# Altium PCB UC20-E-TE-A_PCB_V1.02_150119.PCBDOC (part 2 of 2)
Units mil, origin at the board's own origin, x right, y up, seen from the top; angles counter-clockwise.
Board outline 1460.63 x 2271.65 mil, 4 copper layers (Top, Inner Layer 2, Inner Layer 3, Bottom), stack 35.4 mil thick; 44 components, 79 nets, 323 pads, 599 vias.
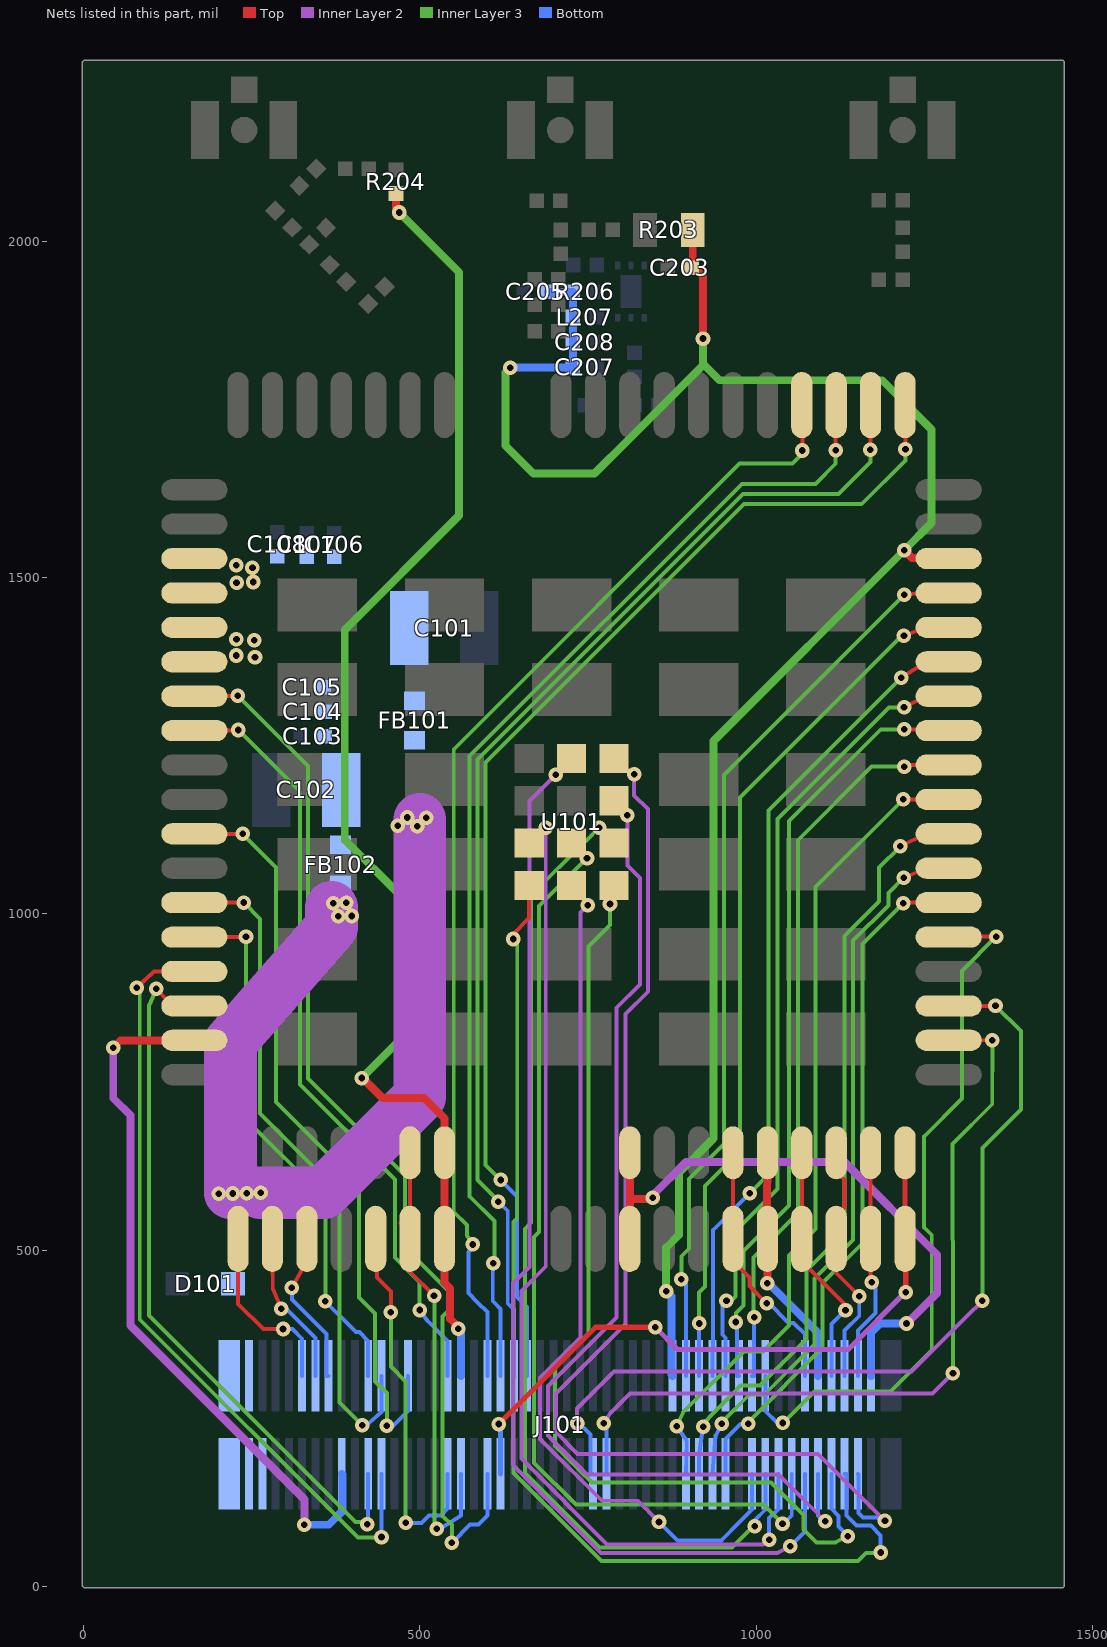
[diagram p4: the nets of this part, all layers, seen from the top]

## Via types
v1: diameter 21.65, hole 9.84, Top to Bottom, 599 vias

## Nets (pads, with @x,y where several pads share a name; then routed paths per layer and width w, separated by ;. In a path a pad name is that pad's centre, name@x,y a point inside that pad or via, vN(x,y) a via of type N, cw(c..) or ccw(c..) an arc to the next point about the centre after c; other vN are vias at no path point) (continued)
JTAG_RESOUT_N: J101.9 U101.100 | length 1483.6
  Top w5.91: v1(782.85,1014.91) 782.85,1038.69 786.63,1042.47 U101.100@788.64,1042.47
  Inner Layer 3 w5.91: v1(782.85,1014.91) 782.85,983.52 750.83,951.5 750.83,376.92 701.05,327.15 701.05,209.44 755.77,154.71 1022.55,154.71 1070.94,106.32 1070.94,84.29 1089.99,65.25 1118,65.25 ; 1118.01,65.26 v1(1136.59,74.65)
  Bottom w5.91: J101.9@1112.2,167.32 1112.2,115.42 1122.71,104.91 1122.71,88.74 v1(1136.59,74.65)
JTAG_RTCK: J101.13 U101.90 | length 1672.4
  Top w5.91: v1(702.23,1207.32) U101.90@725.64,1231.44
  Inner Layer 2 w5.91: v1(702.23,1207.32) 663.08,1168.18 663.08,474.67 638.62,450.21 638.62,180.75 769.65,49.72 1032.32,49.72 v1(1050.69,59.33)
  Bottom w5.91: v1(1050.69,59.33) 1072.83,81.47 J101.13@1072.83,167.32
JTAG_TCK: J101.15 U101.96 | length 1485.7
  Top w3.94: U101.96@725.64,1105.46 726.01,1105.09 738.08,1093.02 v1(748.61,1083.02)
  Top w5.91: U101.96@725.64,1105.46 726.01,1105.46 726.01,1105.09 726.01,1101.59 727.74,1101.59 v1(748.61,1083.02)
  Inner Layer 3 w5.91: v1(748.61,1083.02) 677.43,1011.84 677.43,527.3 670.01,519.88 670.01,183.32 731.93,121.4 1011.31,121.4 v1(1039.41,93.31)
  Bottom w5.91: v1(1039.41,93.31) 1041.24,93.31 1053.15,105.22 J101.15@1053.15,167.32
JTAG_TDI: J101.19 U101.97 | length 1522.4
  Top w5.91: v1(766.75,1128.28) U101.97@788.64,1105.46
  Inner Layer 3 w5.91: v1(766.75,1128.28) 746.96,1108.5 746.25,1108.5 665.62,1027.87 665.62,540.87 656.55,531.8 656.55,168.7 767.49,57.76 964.27,57.76 995.59,89.08 v1(997.94,89.08)
  Bottom w5.91: v1(997.94,89.08) 997.94,98.04 1013.78,113.88 J101.19@1013.78,167.32
JTAG_TDO: J101.11 U101.94 | length 1557.8
  Top w5.91: U101.94@788.64,1168.45 v1(808.74,1146.88)
  Inner Layer 2 w5.91: v1(808.74,1146.88) 808.74,1072.38 827.32,1053.8 827.32,895.41 792.47,860.55 792.47,399.62 690.58,297.73 690.58,224.32 748.9,166 1033.78,166 v1(1103.02,96.76)
  Bottom w5.91: J101.11@1092.52,167.32 1092.52,105.22 1100.98,96.76 v1(1103.02,96.76)
JTAG_TMS: J101.17 U101.95 | length 1515.7
  Top w5.91: U101.95@662.65,1105.46 668.75,1111.56 670.54,1111.56 v1(687.28,1128.31)
  Inner Layer 2 w5.91: v1(687.28,1128.31) 687.28,475.48 650.96,439.16 650.96,189.82 778.57,62.2 1010.12,62.2 1017.3,69.38 v1(1019.45,69.41)
  Bottom w5.91: v1(1019.45,69.41) 1019.45,101.3 1033.46,115.31 J101.17@1033.46,167.32
JTAG_TRST: J101.21 U101.99 | length 1310.8
  Top w5.91: U101.99@725.64,1042.47 v1(749.58,1012.85)
  Inner Layer 2 w5.91: v1(749.58,1012.85) 739.09,1002.36 739.09,369.97 678.77,309.64 678.77,219.42 770.92,127.27 824.19,127.27 v1(855.71,95.75)
  Bottom w5.91: v1(855.71,95.75) 883.01,68.45 948.33,68.45 976.46,96.57 994.09,114.24 J101.21@994.09,167.32
NET_MODE: J101.67 U101.5 | length 640
  Top w3.94: U101.5@434.54,486.89 U101.5@434.54,516.64
  Top w5.91: U101.5@434.54,486.89 434.53,479.06 U101.5@434.3,516.88 434.54,516.64 436.52,514.66 436.52,459.07 457.24,438.35 457.24,412.87 v1(456.78,407.39)
  Inner Layer 3 w5.91: v1(456.78,407.39) 457.24,407.39 457.24,326.69 478.96,304.97 v1(478.96,94.28)
  Bottom w5.91: v1(478.96,94.28) 502.36,94.28 513.39,105.3 531.22,105.3 541.34,115.43 J101.67@541.34,167.32
NET_STATUS: J101.65 U101.6 U101.78 | length 758.9
  Top w3.94: U101.6@471.51,540.66 483.04,529.13 U101.6@485.49,526.68
  Top w5.91: U101.6@471.51,540.66 U101.6@481.76,540.66 ; U101.78@485.49,644.83 U101.6@485.49,540.66 ; v1(521.12,432.36) 485.6,467.87 485.6,516.76 U101.6@485.49,516.88 ; U101.6@481.76,540.66 U101.6@485.48,540.66 ; U101.6@481.76,540.66 483.04,529.13 484.41,516.76 485.49,507.03 U101.6@485.49,516.88 ; U101.6@485.49,516.88 485.49,526.68 U101.6@485.49,540.66
  Inner Layer 3 w5.91: v1(521.12,432.36) 521.6,431.88 521.6,89.16 v1(525.15,85.61)
  Bottom w5.91: v1(525.15,85.61) 526.74,83.14 561.02,105.22 J101.65@561.02,167.32
PCM_CLK: J101.31 U101.27 | length 1229.6
  Top w5.91: v1(1219.03,1170.45) 1253.2,1170.42 U101.27@1286.67,1170.42
  Inner Layer 3 w5.91: v1(882.24,238.19) 891.75,258.92 982.2,349.37 1010.58,349.37 1048.86,387.65 1048.86,492.08 1088.43,531.64 1088.43,1039.85 v1(1219.03,1170.45)
  Bottom w5.91: v1(882.24,238.19) 897.01,216.78 J101.31@895.67,167.32
PCM_IN: J101.25 U101.24 | length 1032.7
  Top w5.91: v1(1218.92,1015.72) 1220.08,1016.88 U101.24@1286.67,1016.88
  Inner Layer 3 w5.91: v1(988.54,241.66) 988.54,244.49 1099.24,355.19 1099.24,450.89 1158.61,510.26 1158.61,955.41 v1(1218.92,1015.72)
  Bottom w5.91: J101.25@954.72,167.32 954.72,219.22 977.16,241.66 v1(988.54,241.66)
PCM_OUT: J101.27 U101.25 | length 1090.2
  Top w5.91: v1(1219.7,1053.91) 1253.2,1068.06 U101.25@1286.67,1068.06
  Inner Layer 3 w5.91: v1(949.15,241.66) 949.15,244.16 989.93,284.95 1012.29,284.95 1087.09,359.74 1087.09,457.96 1144.4,515.27 1144.4,960.37 1196.82,1012.8 1196.82,1031.03 v1(1219.7,1053.91)
  Bottom w5.91: J101.27@937.99,167.32 J101.27@935.04,167.32 939.96,224.14 v1(949.15,241.66) v1@947.15,244.09
PCM_SYNC: J101.29 U101.26 | length 1150
  Top w5.91: v1(1214.72,1100.65) 1253.2,1119.24 U101.26@1286.67,1119.24
  Inner Layer 3 w5.91: v1(921.63,237.53) 919.85,239.13 933.07,253.84 968.82,290.07 977.14,298.58 1006.12,298.58 1075.21,367.68 1075.21,469.84 1131.76,526.39 1131.76,967.16 1183.08,1018.48 1183.08,1069.01 v1(1214.72,1100.65)
  Bottom w5.91: J101.29@915.35,167.32 915.35,194.76 920.91,237.62 v1(921.63,237.53)
PS_HOLD: J101.7 U101.98 | length 1650.6
  Top w5.91: v1(638.88,962.83) 638.88,967.32 637.57,968.64 662.65,993.71 U101.98@662.65,1042.47
  Inner Layer 3 w5.91: v1(638.88,962.83) 637.59,962.83 637.59,962.67 638.16,962.11 644.88,955.38 644.88,547.87 639.27,542.26 639.27,168.88 770.24,37.91 1151.73,37.91 1163.45,49.63 1185.5,49.63 v1(1185.5,50.28)
  Bottom w5.91: J101.7@1131.89,167.32 1134.84,167.32 1134.84,105.22 1149.7,90.37 1170.96,90.37 1185.5,75.83 v1(1185.5,50.28)
PWRKEY: J101.45 U101.21 | length 1336.6
  Top w5.91: U101.21@1286.67,863.33 1320.13,863.33 v1(1356.24,863.47)
  Inner Layer 2 w5.91: v1@741.77,242.5 734.14,242.5 v1(733.89,242.25) 733.89,264.5 788.66,319.28 1231.44,319.28 1313.26,401.1 v1(1336.69,424.55)
  Inner Layer 3 w5.91: v1(1336.69,424.55) 1336.69,651.93 1394.08,709.32 1394.08,825.79 v1(1356.24,863.47)
  Bottom w5.91: v1(733.89,242.25) v1@737.25,242.25 ; v1@737.42,242.25 v1@737.25,242.25 ; J101.45@757.87,167.32 753.98,167.32 753.98,225.53 v1@737.25,242.25
RESERVED: J101.86 U101.3 | length 234
  Top w5.91: v1(309.72,443.86) 331.94,483.41 U101.3@331.94,516.88
  Bottom w5.91: v1(309.72,443.86) 309.68,443.82 309.68,426.89 361.22,375.34 361.22,312.99 J101.86@364.17,312.99
RESET_N: J101.43 U101.20 | length 1215.1
  Top w5.91: U101.20@1286.67,812.15 1315.92,812.15 v1(1351.65,812.43)
  Inner Layer 2 w5.91: v1(773.27,242.73) 783.59,257.83 812.74,286.98 1262.83,286.98 v1(1292.94,317.09)
  Inner Layer 3 w5.91: v1(1292.94,317.09) 1292.94,371.59 1292.09,657.05 1292.09,657.75 1351.38,717.03 v1(1351.65,812.43)
  Bottom w5.91: v1(773.27,242.73) 778.52,237.48 777.56,236.52 J101.43@777.56,167.32
RI: J101.68 U101.62 | length 1196.5
  Top w5.91: U101.62@201.4,1275.08 U101.62@202.18,1275.85 ; U101.62@204.3,1275.85 U101.62@202.18,1275.85 ; v1(230.18,1273.66) 229.3,1272.78 U101.62@164.62,1272.78 167.69,1275.85 U101.62@202.18,1275.85
  Inner Layer 3 w5.91: v1(230.18,1273.66) 321.72,1182.13 321.72,746.54 463.08,605.17 463.08,489.24 499.65,452.68 v1(499.65,410.92)
  Bottom w5.91: v1(499.65,410.92) 511.76,394.47 541.34,364.89 J101.68@541.34,312.99
RTS: J101.74 U101.65 | length 1134.9
  Top w5.91: U101.65@164.62,1119.24 198.08,1119.24 236.56,1119.29 237.22,1119.29 v1(236.56,1119.09)
  Inner Layer 3 w5.91: v1(236.56,1119.09) 286.25,1069.41 286.25,720.46 409.61,597.1 409.61,429.39 433.49,405.5 433.49,304.85 450.96,287.39 v1(450.96,238.73)
  Bottom w5.91: v1(450.96,238.73) 459.92,238.73 482.28,261.09 J101.74@482.28,312.99
RXD: J101.80 U101.68 | length 808.2
  Top w5.91: U101.68@164.62,965.7 198.08,965.7 v1(241.47,966.09)
  Inner Layer 3 w5.91: v1(241.47,966.09) 241.47,694.61 359.33,576.75 v1(359.33,423.73)
  Bottom w5.91: v1(359.33,423.73) 404.92,378.14 409.98,378.14 423.23,364.89 J101.80@423.23,312.99
SD_CLK: J101.30 U101.32 | length 1299.2
  Top w5.91: v1(1220.06,1413.87) 1253.2,1426.33 U101.32@1286.67,1426.33
  Inner Layer 3 w5.91: v1(915.36,390.97) 915.36,437.17 924.38,446.19 924.38,595.16 976.4,647.18 976.4,1173.43 1218.45,1415.48 v1(1220.06,1413.87)
  Bottom w5.91: J101.30@915.35,312.99 915.35,360.24 v1(915.36,390.97)
SD_CMD: J101.32 U101.33 | length 1368.4
  Top w5.91: v1(1220.58,1475.08) 1253.2,1477.51 U101.33@1286.67,1477.51
  Inner Layer 3 w5.91: v1(889,456.75) 889,490.93 900.18,502.12 900.18,606 952.1,657.91 952.1,1206.61 v1(1220.58,1475.08)
  Bottom w5.91: v1(889,456.75) 895.67,450.08 J101.32@895.67,312.99
SD_DATA0: J101.28 U101.31 | length 1232.4
  Top w5.91: v1(1215.98,1351.12) 1253.2,1375.14 U101.31@1286.67,1375.14
  Inner Layer 3 w5.91: v1(990.65,584.42) 1018.69,612.46 1018.69,636.6 1018.6,636.69 1018.6,1153.74 1018.74,1153.74 1215.98,1350.98 v1(1215.98,1351.12)
  Bottom w5.91: J101.28@935.04,312.99 935.04,348.2 936.38,349.54 936.38,530.14 v1(990.65,584.42)
SD_DATA1: J101.26 U101.30 | length 1207.4
  Top w5.91: v1(1220.19,1307.24) 1253.2,1323.96 U101.30@1286.67,1323.96
  Inner Layer 3 w5.91: v1(956.07,424.75) 955.73,417.38 959.58,421.24 969.46,431.12 969.46,528.58 1031.97,591.09 1031.97,1141.14 1198.07,1307.24 v1(1220.19,1307.24)
  Bottom w5.91: J101.26@954.72,312.99 954.72,369.72 950.25,374.2 950.25,421.01 953.99,424.75 v1(956.07,424.75)
SD_DATA2: J101.24 U101.29 | length 1157.3
  Top w5.91: v1(1220.58,1274.67) 1284.78,1274.67 U101.29@1286.67,1272.78
  Inner Layer 3 w5.91: v1(969.94,393.07) 969.94,406.35 981.27,417.68 981.27,498.53 1049.23,566.48 1049.23,1138.33 1185.56,1274.67 v1(1220.58,1274.67)
  Bottom w5.91: v1(969.94,393.07) 971.46,393.07 971.46,312.99 J101.24@974.41,312.99
SD_DATA3: J101.22 U101.28 | length 1100.3
  Top w5.91: v1(1220.58,1219.26) 1220.58,1220.68 1221.5,1221.6 U101.28@1286.67,1221.6
  Inner Layer 3 w5.91: v1(997.51,400.45) 996.26,400.45 996.26,489.13 1062.3,555.17 1062.3,1109.68 1171.87,1219.26 v1(1220.58,1219.26)
  Bottom w5.91: J101.22@994.09,312.99 997.05,312.99 997.05,400.45 v1(997.51,400.45)
SD_DET: J101.20 U101.23 | length 1086.7
  Top w5.91: U101.23@1286.67,965.7 1287.3,966.33 v1(1357.2,966.33)
  Inner Layer 3 w5.91: v1(1039.95,242.99) 1086.96,290 1200.18,290 1261.42,351.23 1261.42,522.66 1250.22,533.86 1250.22,669.23 1306.33,725.33 1306.33,915.46 v1(1357.2,966.33)
  Bottom w5.91: J101.20@1013.78,312.99 1013.78,261.09 1031.89,242.99 v1(1039.95,242.99)
SD_VDD: C203.1 C205.2 C207.2 C208.2 J101.34 L207.1 R203.2 R206.1 U101.34 | length 2977.3
  Top w11.81: C203.1@904.07,1961.29 C203.1@905.93,1961.29 ; R203.2@905.93,2017.38 C203.1@905.93,1961.29 ; v1(921.13,1855.91) 921.13,1948.85 908.69,1961.29 C203.1@905.93,1961.29 ; v1(1220.58,1541.02) 1232.09,1529.51 1254.95,1529.51 1255.77,1528.69 U101.34@1286.67,1528.69
  Inner Layer 3 w11.81: v1(634.37,1812.7) 627.24,1805.58 627.24,1696.54 668.75,1655.04 759.67,1655.04 784.48,1679.84 784.72,1679.84 921.13,1816.25 921.13,1817.65 ; v1(866.38,439) 866.35,503.76 885.24,522.64 885.24,614.25 936.9,665.92 936.9,1257.34 v1(1220.58,1541.02) 1260.98,1581.42 1260.98,1720.59 1187.66,1793.91 945.62,1793.91 921.88,1817.65 921.13,1817.65 ; v1(921.13,1855.91) 921.13,1817.65
  Bottom w11.81: v1(634.37,1812.7) 727.22,1812.7 C207.2@727.65,1813.14 C208.2@727.65,1850.54 L207.1@727.65,1887.94 R206.1@727.65,1925.34 C205.2@690.25,1925.34 ; v1(866.38,439) 874.27,431.11 874.27,314.71 J101.34@875.98,312.99
SIM_CLK: J101.8 U101.16 U101.86 | length 364.9
  Top w5.91: U101.86@1119.34,644.83 1124.48,639.7 1124.48,611.57 1131.31,604.74 1131.31,563.82 1119.34,551.85 U101.16@1119.34,516.88 1119.34,465.76 v1(1153.55,431.55)
  Bottom w5.91: J101.8@1131.89,312.99 1131.89,380.19 1153.55,401.85 v1(1153.55,431.55)
SIM_DATA: J101.10 U101.15 U101.85 | length 367.4
  Top w5.91: U101.85@1068.16,644.83 U101.15@1068.16,516.88 1068.16,483.41 1133.1,418.47 v1(1133.1,410.75)
  Bottom w5.91: J101.10@1112.2,312.99 1112.2,389.85 v1(1133.1,410.75)
SIM_GND: J101.4 U101.10 U101.80 | length 910.8
  Top w11.81: U101.10@812.26,516.88 812.26,575.96 ; U101.80@812.26,644.83 812.26,575.96 ; v1(846.37,578.07) 843.13,577.16 838.63,575.96 812.26,575.96
  Inner Layer 2 w11.81: v1(846.37,578.07) 846.37,581.68 895.93,631.25 1131.5,631.25 1269.55,493.2 1269.55,436.38 1224.1,390.93 v1(1223.82,390.93)
  Bottom w11.81: J101.4@1171.26,312.99 1171.26,377.05 1184.35,390.93 v1(1223.82,390.93)
SIM_PRESENCE: J101.14 U101.13 U101.83 | length 384.1
  Top w5.91: U101.83@965.8,644.83 U101.13@965.8,516.88 965.8,483.41 990.2,459.02 990.2,446.74 v1(1015.95,420.99)
  Bottom w5.91: v1(1015.95,420.99) 1017.74,422.78 1048.58,391.94 1055.99,391.94 1072.83,375.09 J101.14@1072.83,312.99
SIM_RST: J101.6 U101.17 U101.87 | length 353.4
  Top w5.91: U101.87@1170.52,644.83 U101.17@1170.52,516.88 1170.52,453.58 1171.11,451.9 1172.41,448.16 v1(1172.41,452.35)
  Bottom w5.91: J101.6@1151.57,312.99 1151.57,380.84 1177.53,406.8 1177.53,447.23 v1(1172.41,452.35)
SIM_VDD: J101.12 U101.14 U101.84 | length 364
  Top w11.81: v1(1016.82,450.7) 1016.98,483.41 U101.14@1016.98,516.88 1016.98,550.34 1016.68,577.02 1016.98,621.21 U101.84@1016.98,644.83
  Bottom w11.81: v1(1016.82,450.7) 1020.18,449.26 1092.52,376.92 J101.12@1092.52,312.99
SPI_CLK: J101.62 U101.40 | length 1730.4
  Top w5.91: U101.40@1068.16,1757.03 1068.87,1756.33 v1(1068.87,1689.4)
  Inner Layer 3 w5.91: v1(578.6,508.46) 569.92,522.34 569.92,537.31 550.42,556.81 550.42,1244.65 975.55,1669.78 1054.06,1669.78 1068.58,1684.3 1068.58,1689.11 v1(1068.87,1689.4)
  Bottom w5.91: v1(578.6,508.46) 579.26,507.8 579.26,504.35 572.39,497.48 572.39,436.03 586.03,422.39 600.39,408.29 J101.62@600.39,312.99
SPI_CS: J101.56 U101.37 | length 1831
  Top w5.91: U101.37@1221.71,1757.03 1221.71,1727.3 1222.27,1724.21 v1(1222.27,1691)
  Inner Layer 3 w5.91: v1(620.12,604.41) 597.66,626.86 597.66,1225.08 982.15,1609.57 1157.3,1609.57 1222.27,1674.54 v1(1222.27,1691)
  Bottom w5.91: v1(620.12,604.41) 644.83,579.7 644.83,430 659.45,415.38 J101.56@659.45,312.99
SPI_MISO: J101.60 U101.39 | length 1767.2
  Top w5.91: v1(1118.58,1689.72) 1118.58,1728.14 1121,1730.55 1121,1755.38 U101.39@1119.34,1757.03
  Inner Layer 3 w5.91: v1(609.17,480.76) 609.17,475.11 610,480.64 611.09,487.86 611.09,543.11 574.04,580.15 574.04,1234.87 979.03,1639.86 1088.66,1639.86 1118.58,1669.78 v1(1118.58,1689.72)
  Bottom w5.91: v1(609.17,480.76) 608.48,477.55 608.48,477.37 608.43,477.32 608.43,424.17 620.08,412.52 J101.60@620.08,312.99
SPI_MOSI: J101.58 U101.38 | length 1791.8
  Top w5.91: v1(1170.14,1690.67) 1170.52,1691.05 U101.38@1170.52,1757.03
  Inner Layer 3 w5.91: v1(616.55,572.17) 616.55,573.75 585.85,604.45 585.85,1229.97 980.71,1624.83 1122.74,1624.83 1170.14,1672.23 v1(1170.14,1690.67)
  Bottom w5.91: v1(616.55,572.17) 630.77,557.94 630.77,420.7 639.76,411.71 J101.58@639.76,312.99
STATUS: J101.61 U101.61 | length 1596
  Top w5.91: U101.61@164.62,1323.96 228.2,1323.96 v1(228.95,1324.71)
  Inner Layer 3 w5.91: v1(228.95,1324.71) 333.54,1220.12 333.54,755.44 478.02,610.96 478.02,505.74 478.84,504.92 478.84,503.31 542.78,439.37 542.78,410.21 533.79,401.22 533.79,104.81 547.5,91.1 v1(547.5,64.57)
  Bottom w5.91: v1(547.5,64.57) 574.82,91.89 587.06,91.89 600.39,105.22 J101.61@600.39,167.32
TXD: J101.78 U101.67 | length 1013.9
  Top w5.91: U101.67@164.62,1016.88 198.08,1016.88 v1(238.35,1017.05)
  Inner Layer 3 w5.91: v1(238.35,1017.05) 262.57,992.82 262.57,703.24 380.71,585.1 380.71,273.18 v1(414.19,239.7)
  Bottom w5.91: v1(414.19,239.7) 421.13,239.7 442.91,259.22 J101.78@442.91,312.99
USB_DM: J101.79 U101.70 | length 1084.8
  Top w5.91: v1(108.18,888.89) 131.15,863.33 U101.70@164.62,863.33
  Inner Layer 3 w5.91: v1(108.18,888.89) 97.18,863.58 97.18,402.81 404.45,95.54 418.79,95.54 v1(421.91,92.42)
  Bottom w5.91: v1(421.91,92.42) 423.23,94.44 J101.79@423.23,167.32
USB_DP: J101.77 U101.69 | length 1189.4
  Top w5.91: v1(78.79,890.29) 104.73,914.51 U101.69@164.62,914.51
  Inner Layer 3 w5.91: v1(78.79,890.29) 77.49,890.29 78.14,889.64 83.4,884.38 83.4,397.1 407.77,72.73 442.36,72.73 v1(442.94,73.31)
  Bottom w5.91: J101.77@442.91,167.32 v1@442.91,73.31 ; v1@442.91,73.31 442.91,68.87 v1(442.94,73.31)
USB_VBUS: J101.83 U101.71 | length 1073.4
  Top w11.81: v1(43.99,801.1) 55.04,812.15 U101.71@164.62,812.15
  Inner Layer 2 w11.81: v1(43.99,801.1) 43.99,726.11 69.48,700.62 69.48,387.87 328.31,129.04 v1(328.31,91.57)
  Bottom w11.81: v1(328.31,91.57) 364.51,91.57 385,112.06 385,166.18 J101.83@383.86,167.32
VBAT: D101.1 FB101.1 FB102.1 J101.95 J101.97 J101.98 J101.99 J101.100 | length 1188.9
  Inner Layer 2 w78.74: v1@218.22,585.38 218.22,809.69 368.91,981.06 368.91,996.72 368.91,996.98 v1@368.91,1009.36 ; v1(263.15,585.38) 357.26,585.38 499.91,728.03 499.91,1130.56 499.91,1131.05 v1@499.91,1140.31
  other v1: 200.96,583.98 221.77,584.24 242.6,584.58 378.54,996.72 398.9,996.98 371.02,1015.72 390.67,1016.75 467.18,1131.05 495.89,1130.56 481.31,1143.56 509.82,1143.43
VBAT_BB: C102.1 C103.1 C104.1 C105.1 FB102.2 U101.59 U101.60
  other v1: 254.82,1382.06 226.73,1384.51 253.83,1407.18 227.23,1408.65
VBAT_RF: C101.1 C106.1 C107.1 C108.1 FB101.2 U101.57 U101.58
  other v1: 227.35,1492.49 252.27,1493.83 251.04,1515.01 227.17,1518.46
VDD_EXT: J101.66 R204.2 U101.7 U101.79 | length 2028.3
  Top w11.81: v1(413.48,756) 414.09,756.61 444.41,726.3 506.47,726.3 536.67,696.11 U101.79@536.67,644.83 U101.7@536.67,516.88 536.67,451.48 545.07,443.08 545.07,397.92 556.93,386.05 v1(556.93,383.03) ; R204.2@464.53,2071.61 464.53,2043.4 v1(469.32,2043.4)
  Inner Layer 3 w11.81: v1(413.48,756) 472.05,814.57 472.05,1026.59 388.27,1110.37 388.27,1422.56 558.36,1592.65 558.36,1954.36 v1(469.32,2043.4)
  Bottom w11.81: v1(556.93,383.03) 561.02,378.33 J101.66@561.02,312.99
VRTC: J101.59 U101.18 U101.88 | length 999.7
  Top w5.91: U101.18@1221.71,516.88 1223.56,515.03 U101.18@1223.56,505.45
  Top w7.87: v1(617.38,241.38) 761.34,385.34 v1(850.2,385.34) ; U101.18@1221.71,516.88 U101.88@1221.71,644.83 ; v1(1222.73,437.45) U101.18@1222.73,504.62
  Top w11.81: U101.18@1222.73,504.62 U101.18@1223.56,505.45
  Inner Layer 2 w7.87: v1(850.2,385.34) 883.29,352.24 1137.19,352.24 1222.57,437.61 v1@1222.73,437.78
  Inner Layer 2 w11.81: v1(1222.73,437.45) v1@1222.73,437.78
  Bottom w7.87: v1(617.38,241.38) 620.08,241.38 J101.59@620.08,167.32
WAKEUP_IN: J101.90 U101.1 | length 269.1
  Top w5.91: U101.1@229.91,516.55 U101.1@229.58,516.88 229.58,420.25 267.15,382.68 v1(296.52,382.75)
  Bottom w5.91: v1(296.52,382.75) 310.27,382.75 324.8,368.22 J101.90@324.8,312.99
WAKEUP_OUT: J101.88 U101.2 | length 231.2
  Top w5.91: U101.2@280.76,516.88 280.76,483.41 281.21,442.92 v1(294.07,412.97)
  Bottom w5.91: v1(294.07,412.97) 300.61,412.97 344.49,369.09 J101.88@344.49,312.99
WDOG_DISABLE: J101.5 U101.91 | length 1729
  Top w5.91: U101.91@788.64,1231.44 v1(818.73,1207.69)
  Inner Layer 2 w5.91: v1(818.73,1207.69) 818.73,1176.32 839.13,1155.91 839.13,884.36 805.93,851.15 805.93,390.33 702.39,286.78 702.39,229.21 734.54,197.06 1092.11,197.06 v1(1191.8,97.37)
  Bottom w5.91: J101.5@1151.57,167.32 1152.2,166.69 1152.2,108.85 1158.87,102.18 1186.99,102.18 v1(1191.8,97.37)
pads on no net: J101.18 J101.23 J101.36 J101.41 J101.44 J101.46 J101.48 J101.50 J101.52 J101.57 J101.63 J101.69 J101.71 J101.73 J101.85 J101.87 J101.89 U101.43 U101.73 U101.74 U101.75 U101.76 U101.77 U101.89 U101.93

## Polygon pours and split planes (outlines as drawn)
GND on Top "Top-GND" (solid, pour order 1000): 310,1660 1175,1660 1175,760 1150,735 1130,715 325,715 310,715 270,755 270,1645 291.04,1666.04 314.7,1666.04
GND on Top "Top-GND" (solid, remove dead copper, pour order 1000): -80.96,2329.75 1598.18,2329.75 1598.18,-24.58 -80.96,-24.58
GND on Top "Top-GND" (solid, pour order 1000): 135,2250 1320,2250 1320,1925 1285,1890 1240,1845 655,1845 180,1845 130,1895 145,1910 145,2250
GND on Inner Layer 2 "Inner Layer 2-GND" (solid, remove dead copper, pour order 1001): -128.46,2299.92 1560.51,2299.92 1560.51,-80 -128.46,-80
GND on Inner Layer 3 "Inner Layer 3-GND" (solid, remove dead copper, pour order 1002): -102.87,2299.92 1560.51,2299.92 1560.51,-48.5 -102.87,-48.5
GND on Bottom "Bottom-GND" (solid, remove dead copper, pour order 1003): -124.53,2299.92 1564.45,2299.92 1564.45,-58.35 -124.53,-58.35

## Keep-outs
Keep-Out Layer:
  lines w3.94: 0,0 0,2267.72 1456.69,2267.72 1456.69,0 0,0

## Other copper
Top:
  pour cut-out: 201.04,2206.05 274.84,2206.05 274.84,2081.86 201.04,2081.86 201.04,2206.05
  region net VBAT_RF: 185.92,1544.67 270.66,1544.67 270.66,1462.6 185.92,1462.6 185.92,1544.67
  pour cut-out: 1237.35,1957.18 1389.08,1805.45 1389.08,1587.69 1353.23,1551.84 1226.81,1551.84 1226.81,1608.27 1331.86,1608.27 1346.19,1622.59 1346.19,1784.29 1199.27,1931.21 1199.27,1956.68 1237.35,1956.68 1237.35,1957.18
  region net GND: 742.34,1819.02 783.94,1819.02 783.94,1691.71 742.34,1691.71 742.34,1819.02
  pour cut-out: 289.96,2074.48 422.78,1941.65 389.36,1908.23 251.56,2046.04 289.96,2074.48
  pour cut-out: 681.08,1813.79 740.24,1813.79 740.24,1695.81 681.08,1695.81 681.08,1813.79
  pour cut-out: 672.07,2206.04 745.88,2206.04 745.88,2081.85 672.07,2081.85 672.07,2206.04
  region net GND: 519.9,1824.61 569.06,1824.61 569.06,1684.87 519.9,1684.87 519.9,1824.61
  region net GND: 1219.37,1669.66 1344.15,1669.66 1344.15,1625.24 1329.57,1610.66 1219.37,1610.66 1219.37,1669.66
  region net VBAT_BB: 186.56,1440.79 271.61,1440.79 271.61,1358.22 186.56,1358.22 186.56,1440.79
  pour cut-out: 1199.19,2083.69 1237.86,2083.69 1237.86,1931.01 1199.19,1931.01 1199.19,2083.69
  pour cut-out: 1181.06,2204.57 1254.87,2204.57 1254.87,2080.38 1181.06,2080.38 1181.06,2204.57
  pour cut-out: 452.77,1814.46 519.9,1814.46 519.9,1694.63 452.77,1694.63 452.77,1814.46
  pour cut-out: 683.33,2060.38 734.8,2060.38 734.8,1811.19 683.33,1811.19 683.33,2060.38
  region net GND: 365.34,1822.74 452.77,1822.74 452.77,1682.39 365.34,1682.39 365.34,1822.74
Inner Layer 2:
  pour cut-out: 661.42,2206.14 755.91,2206.14 755.91,1695.29 661.42,1695.29 661.42,2206.14
  region net VBAT: 326.6,1056.1 409.74,1056.1 409.74,976.46 326.6,976.46 326.6,1056.1
  pour cut-out: 192.91,2205.79 284.45,2205.79 284.45,2072.85 192.91,2072.85 192.91,2205.79
  pour cut-out: 1235.67,1598.43 1336.05,1598.43 1336.05,1561.19 1235.67,1561.19 1235.67,1598.43
  pour cut-out: 1239.15,2089.44 1196.36,2089.44 1196.36,2185.59 1239.15,2185.59 1239.15,2089.44
  pour cut-out: 1206.82,1954.74 1229.57,1954.74 1229.57,1931.65 1206.82,1931.65 1206.82,1954.74
  pour cut-out: 207.03,2078.67 264.46,2136.1 533.07,1872.53 533.07,1694.63 438.58,1694.63 438.58,1821.34 193.4,2072.07 193.4,2132.23 207.03,2132.23 207.03,2078.67
  pour cut-out: 1206.5,1996.05 1228.91,1996.05 1228.91,1973.14 1206.5,1973.14 1206.5,1996.05
  region net VBAT: 176.22,626.93 278.74,626.93 278.74,541.34 176.22,541.34 176.22,626.93
  pour cut-out: 1206.5,2031.9 1228.91,2031.9 1228.91,2009.49 1206.5,2009.49 1206.5,2031.9
  region net VBAT: 457.61,1271.75 542.2,1271.75 542.2,1100.94 457.61,1100.94 457.61,1271.75
  pour cut-out: 1205.87,2073.2 1229.74,2073.2 1229.74,2049.99 1205.87,2049.99 1205.87,2073.2
Bottom:
  region net VBAT: 162.87,355.04 174.69,366.85 251.46,366.85 251.46,248.74 269.17,231.02 269.17,112.91 162.87,112.91 162.87,355.04
  pour cut-out: 798.1,1895.01 837.39,1895.01 837.39,1738.95 798.1,1738.95 798.1,1895.01
  region net VBAT_BB: 200.14,1424.41 362.19,1424.41 415.63,1370.97 415.63,1089.97 346.33,1089.97 346.33,1353.11 337.46,1361.98 200.14,1361.98 200.14,1424.41
  pour cut-out: 695.38,1775.12 796.88,1775.12 796.88,1737.95 695.38,1737.95 695.38,1775.12
  region net VBAT_RF: 456.06,1306.19 456.06,1454.53 446.28,1464.32 194.54,1464.32 194.54,1547.64 472.53,1547.64 523.5,1496.67 523.5,1304.28 458.11,1304.28 458.11,1306.19 456.06,1306.19
  region net VBAT: 457.38,1271.75 542.2,1271.75 542.2,1101.43 457.38,1101.43 457.38,1271.75
  region net VBAT: 175.24,365.98 175.24,626.27 279.65,626.27 279.65,483.2 251.43,454.99 251.43,365.98 175.24,365.98
  pour cut-out: 759.63,1810.45 801.17,1810.45 801.17,1741.13 759.63,1741.13 759.63,1810.45
  region net VBAT: 327.07,1056.68 410.79,1056.68 410.79,976.33 327.07,976.33 327.07,1056.68

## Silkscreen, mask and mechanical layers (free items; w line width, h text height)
Silkscreen Top:
  lines w3.94: 232.28,15.75 1216.54,15.75 1216.54,409.45 232.28,409.45 232.28,15.75
  text "MAIN" at 414.07,2188.14 h29.53
  text "GPS" at 811.01,2187.11 h29.53
  text "DIV" at 1317.83,2180.16 h29.53
  text "54" at 212.15,1831.51 h23.62
  text "37" at 1206.15,1824.42 h23.62
  text "36" at 1357.73,1625.75 h23.62
  text "55" at 49.61,1612.2 h23.62
  text "63" at 56.98,1207.03 h23.62
  text "27" at 1352.44,1152.97 h23.62
  text "19" at 1358.14,744.3 h23.62
  text "72" at 53.03,744.27 h23.62
  text "18" at 1213.35,417.39 h23.62
  text "1" at 224.42,414.5 h23.62
  text "LABEL POSITION" at 433.86,195.62 h50
Silkscreen Bottom:
  text "V1.02" at 137.19,810.43 h29.53
Paste Mask Bottom:
  lines w23.62: 27.93,927.07 27.93,962.51 ; 27.93,997.94 27.93,1049.12 ; 27.93,1084.55 27.93,1135.73 ; 27.93,1171.17 27.93,1222.35 ; 27.93,1257.78 27.93,1308.96 ; 27.93,1344.4 27.93,1395.58 ; 27.93,1431.01 27.93,1482.19 ; 27.93,1517.62 27.93,1568.81 ; 27.93,1604.24 27.93,1655.42 ; 27.93,1690.85 27.93,1742.03 ; 27.93,1777.47 27.93,1828.65 ; 27.93,1864.08 27.93,1915.26 ; 27.93,1950.7 27.93,2001.88 ; 27.93,2037.31 27.93,2088.49 ; 60.26,2089.16 118.92,2089.16 ; 62.87,929.38 125.87,929.38 ; 177.17,929.13 240.16,929.13 ; 177.17,2090.55 228.35,2090.55 ; 263.78,2090.55 314.96,2090.55 ; 275.59,929.13 326.77,929.13 ; 350.39,2090.55 401.57,2090.55 ; 362.2,929.13 413.39,929.13 ; 437.01,2090.55 488.19,2090.55 ; 448.82,929.13 500,929.13 ; 523.62,2090.55 574.8,2090.55 ; 535.43,929.13 586.61,929.13 ; 610.24,2090.55 661.42,2090.55 ; 622.05,929.13 673.23,929.13 ; 696.85,2090.55 748.03,2090.55 ; 708.66,929.13 759.84,929.13 ; 783.46,2090.55 834.65,2090.55 ; 795.28,929.13 846.46,929.13 ; 870.08,2090.55 921.26,2090.55 ; 881.89,929.13 933.07,929.13 ; 956.69,2090.55 1007.87,2090.55 ; 968.5,929.13 1019.69,929.13 ; 1043.31,2090.55 1094.49,2090.55 ; 1055.12,929.13 1106.3,929.13 ; 1129.92,2090.55 1181.1,2090.55 ; 1141.73,929.13 1192.91,929.13 ; 1216.54,2090.55 1267.72,2090.55 ; 1228.35,929.13 1279.53,929.13 ; 1307.19,2089.13 1384.4,2089.13 ; 1328.95,929.48 1380.13,929.48 ; 1429.99,927.19 1429.99,962.62 ; 1429.99,998.06 1429.99,1049.24 ; 1429.99,1084.67 1429.99,1135.85 ; 1429.99,1171.29 1429.99,1222.47 ; 1429.99,1257.9 1429.99,1309.08 ; 1429.99,1344.51 1429.99,1395.7 ; 1429.99,1431.13 1429.99,1482.31 ; 1429.99,1517.74 1429.99,1568.92 ; 1429.99,1604.36 1429.99,1655.54 ; 1429.99,1690.97 1429.99,1742.15 ; 1429.99,1777.59 1429.99,1828.77 ; 1429.99,1864.2 1429.99,1915.38 ; 1429.99,1950.81 1429.99,2001.99 ; 1429.99,2037.43 1429.99,2088.61
Solder Mask Bottom:
  lines w27.56: 27.56,929.13 27.56,2090.55 1429.13,2090.55 1429.13,929.13 27.56,929.13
